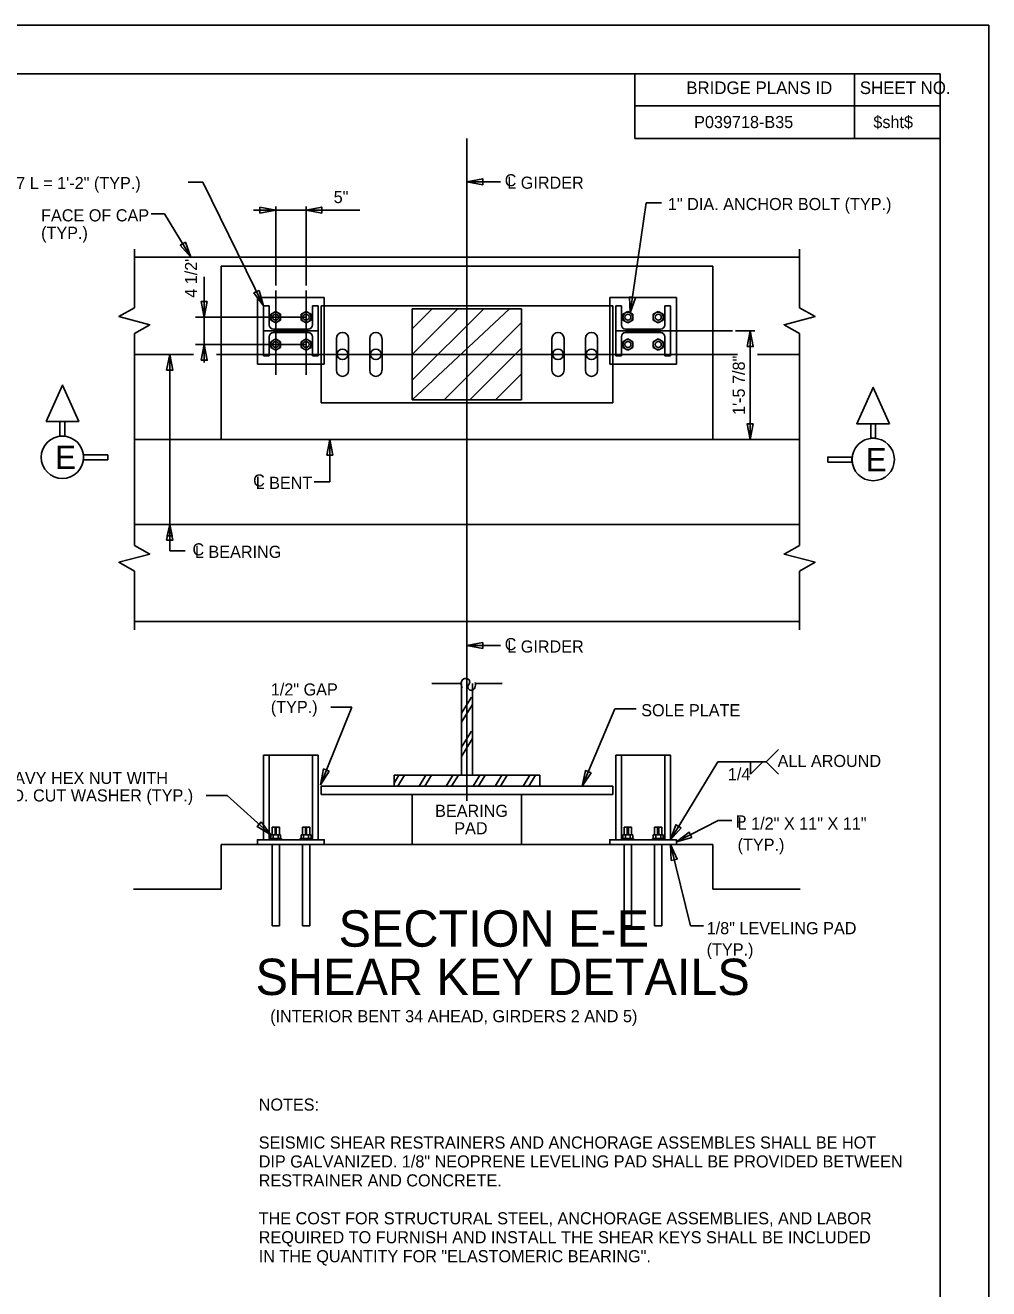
# Model space of a CAD drawing. Extents: x -144.4 to -96.3, y -117.1 to -87.8.
# Drawn here: x -109.69 to -96.47, y -105.14 to -87.8 of the extents above; entities that cross this region are included whole.
import ezdxf

# ---------------------------------------------------------------- set-up
doc = ezdxf.new("R2010")
doc.units = 0
for name, color, linetype in [('BR_AUTO DIMENSION', 7, 'Continuous'), ('BR_BORDER LINES', 7, 'Continuous'), ('BR_CENTER LINE BASELINE', 7, 'Continuous'), ('BR_CENTER LINES', 7, 'Continuous'), ('BR_CONCRETE', 7, 'Continuous'), ('BR_STRUCTURAL STEEL', 7, 'Continuous'), ('BR_TABLE LINES', 7, 'Continuous'), ('BR_TEXT', 7, 'Continuous'), ('Default', 7, 'Continuous'), ('Level 31', 7, 'Continuous')]:
    doc.layers.add(name, color=color, linetype=linetype)

msp = doc.modelspace()

# ---------------------------------------------------------------- linework, layer by layer
at = {"layer": 'BR_AUTO DIMENSION'}
for p, q in [((-107.459, -89.956), (-107.259, -89.956)), ((-107.259, -89.956), (-106.423, -91.651)), ((-103.632, -89.949), (-103.172, -89.949)), ((-106.257, -91.371), (-106.257, -90.287)), ((-105.84, -91.371), (-105.84, -90.287)), ((-101.39, -91.748), (-101.174, -90.239)), ((-101.174, -90.239), (-100.961, -90.239)), ((-107.966, -90.388), (-107.781, -90.388)), ((-107.781, -90.388), (-107.42, -90.984)), ((-106.562, -90.338), (-105.104, -90.338)), ((-108.195, -91.677), (-108.195, -90.874)), ((-99.068, -91.677), (-99.068, -90.874)), ((-107.238, -91.252), (-107.238, -92.429)), ((-108.195, -92.854), (-108.195, -92.031)), ((-99.946, -91.995), (-99.681, -91.995)), ((-99.743, -91.995), (-99.743, -93.484)), ((-99.068, -92.854), (-99.068, -92.031)), ((-107.712, -95.011), (-107.712, -92.317)), ((-108.195, -92.854), (-108.195, -94.114)), ((-99.068, -92.854), (-99.068, -94.114)), ((-105.515, -94.065), (-105.515, -93.484)), ((-99.881, -93.484), (-99.681, -93.484)), ((-108.195, -94.114), (-108.195, -94.937)), ((-105.728, -94.065), (-105.515, -94.065)), ((-99.068, -94.114), (-99.068, -94.937)), ((-107.499, -95.011), (-107.712, -95.011)), ((-108.195, -95.291), (-108.195, -96.094)), ((-99.068, -95.291), (-99.068, -96.094)), ((-103.632, -96.312), (-103.172, -96.312)), ((-105.214, -97.155), (-105.64, -98.221)), ((-105.502, -97.155), (-105.214, -97.155)), ((-101.601, -97.18), (-102.051, -98.241)), ((-101.309, -97.18), (-101.601, -97.18)), ((-99.356, -97.738), (-99.525, -97.906)), ((-100.188, -97.906), (-100.84, -98.975)), ((-100.188, -97.906), (-99.525, -97.906)), ((-99.572, -97.906), (-99.74, -98.074)), ((-99.74, -97.906), (-99.74, -98.074)), ((-99.525, -97.906), (-99.356, -98.074)), ((-107.211, -98.369), (-106.923, -98.369)), ((-106.923, -98.369), (-106.324, -98.907)), ((-104.382, -98.354), (-104.382, -99.042)), ((-104.382, -98.354), (-102.882, -98.354)), ((-102.882, -98.354), (-102.882, -99.042)), ((-100.182, -98.711), (-100.757, -99.005)), ((-99.996, -98.711), (-100.182, -98.711)), ((-100.838, -99.042), (-100.563, -100.157)), ((-100.563, -100.157), (-100.386, -100.157))]:
    msp.add_line(p, q, dxfattribs=at)
for points in [[(-103.416, -89.991), (-103.632, -89.949), (-103.416, -89.907)], [(-106.473, -90.297), (-106.257, -90.338), (-106.473, -90.38)], [(-105.624, -90.38), (-105.84, -90.338), (-105.624, -90.297)], [(-107.497, -90.778), (-107.42, -90.984), (-107.568, -90.821)], [(-106.482, -91.439), (-106.423, -91.651), (-106.556, -91.475)], [(-107.196, -91.591), (-107.238, -91.807), (-107.279, -91.591)], [(-101.318, -91.54), (-101.39, -91.748), (-101.4, -91.529)], [(-99.785, -92.211), (-99.743, -91.995), (-99.702, -92.211)], [(-107.279, -92.398), (-107.238, -92.182), (-107.196, -92.398)], [(-107.754, -92.534), (-107.712, -92.317), (-107.671, -92.534)], [(-99.702, -93.268), (-99.743, -93.484), (-99.785, -93.268)], [(-105.557, -93.7), (-105.515, -93.484), (-105.474, -93.7)], [(-107.754, -94.867), (-107.712, -94.651), (-107.671, -94.867)], [(-107.676, -94.807), (-107.712, -94.651), (-107.748, -94.807)], [(-103.416, -96.353), (-103.632, -96.312), (-103.416, -96.27)], [(-105.522, -98.036), (-105.64, -98.221), (-105.599, -98.005)], [(-101.928, -98.058), (-102.051, -98.241), (-102.005, -98.026)], [(-106.457, -98.732), (-106.324, -98.907), (-106.513, -98.794)], [(-100.692, -98.812), (-100.84, -98.975), (-100.763, -98.769)], [(-100.545, -98.944), (-100.757, -99.005), (-100.583, -98.87)], [(-100.827, -99.262), (-100.838, -99.042), (-100.746, -99.242)]]:
    msp.add_lwpolyline(points, close=True, dxfattribs=at)
for points in [[(-108.195, -91.677), (-108.41, -91.8), (-107.985, -91.911), (-108.195, -92.031)], [(-99.068, -91.677), (-98.853, -91.8), (-99.279, -91.911), (-99.068, -92.031)], [(-108.195, -95.291), (-108.41, -95.168), (-107.985, -95.057), (-108.195, -94.937)], [(-99.068, -95.291), (-98.853, -95.168), (-99.279, -95.057), (-99.068, -94.937)]]:
    msp.add_lwpolyline(points, dxfattribs=at)
at = {"layer": 'BR_BORDER LINES'}
for p, q in [((-97.136, -88.468), (-141.912, -88.468)), ((-101.329, -89.354), (-101.329, -88.468)), ((-98.315, -89.354), (-98.315, -88.468)), ((-97.136, -116.398), (-97.136, -88.468)), ((-101.329, -88.906), (-97.136, -88.906)), ((-98.315, -88.906), (-97.136, -88.906)), ((-97.136, -89.354), (-101.329, -89.354))]:
    msp.add_line(p, q, dxfattribs=at)
at = {"layer": 'BR_CENTER LINE BASELINE'}
for centre in [(-105.34, -92.317), (-104.882, -92.317), (-102.382, -92.317), (-101.923, -92.317)]:
    msp.add_circle(centre, 0.0729, dxfattribs=at)
at = {"layer": 'BR_CENTER LINES'}
for p, q in [((-103.632, -89.354), (-103.632, -98.44)), ((-106.257, -91.439), (-106.257, -92.6)), ((-105.84, -91.439), (-105.84, -92.6)), ((-105.84, -91.807), (-107.36, -91.807)), ((-100.84, -91.995), (-99.989, -91.995)), ((-105.84, -92.182), (-107.36, -92.182)), ((-108.195, -92.317), (-107.383, -92.317)), ((-107.07, -92.317), (-99.917, -92.317)), ((-99.645, -92.317), (-99.068, -92.317)), ((-99.068, -93.484), (-108.195, -93.484)), ((-108.195, -94.651), (-99.068, -94.651))]:
    msp.add_line(p, q, dxfattribs=at)
at = {"layer": 'BR_CONCRETE'}
for p, q in [((-108.195, -90.984), (-99.068, -90.984)), ((-107.007, -91.109), (-100.257, -91.109)), ((-107.007, -93.484), (-107.007, -91.109)), ((-100.257, -93.484), (-100.257, -91.109)), ((-107.007, -93.484), (-100.257, -93.484)), ((-108.195, -95.984), (-99.068, -95.984)), ((-107.007, -99.042), (-107.007, -99.653)), ((-107.007, -99.042), (-100.257, -99.042)), ((-100.257, -99.042), (-100.257, -99.653)), ((-107.007, -99.653), (-108.207, -99.653)), ((-99.057, -99.653), (-100.257, -99.653))]:
    msp.add_line(p, q, dxfattribs=at)
at = {"layer": 'BR_STRUCTURAL STEEL'}
for p, q in [((-106.507, -91.536), (-106.507, -92.453)), ((-105.59, -91.536), (-106.507, -91.536)), ((-106.345, -91.651), (-106.423, -91.651)), ((-106.423, -91.651), (-106.423, -92.338)), ((-106.345, -91.651), (-106.345, -91.914)), ((-105.673, -91.651), (-105.751, -91.651)), ((-105.751, -91.651), (-105.751, -91.914)), ((-105.673, -91.651), (-105.673, -92.338)), ((-105.632, -91.651), (-105.632, -92.984)), ((-101.632, -91.651), (-105.632, -91.651)), ((-105.59, -91.536), (-105.59, -91.651)), ((-105.59, -91.651), (-105.59, -92.453)), ((-101.673, -91.536), (-101.673, -91.651)), ((-101.673, -91.536), (-100.757, -91.536)), ((-101.673, -91.651), (-101.673, -92.453)), ((-101.632, -91.651), (-101.632, -92.984)), ((-101.59, -91.651), (-101.59, -92.338)), ((-101.59, -91.651), (-101.512, -91.651)), ((-101.512, -91.651), (-101.512, -91.914)), ((-100.918, -91.651), (-100.918, -91.914)), ((-100.918, -91.651), (-100.84, -91.651)), ((-100.84, -91.651), (-100.84, -92.338)), ((-100.757, -91.536), (-100.757, -92.453)), ((-106.257, -91.729), (-106.324, -91.768)), ((-106.324, -91.846), (-106.324, -91.768)), ((-106.257, -91.885), (-106.324, -91.846)), ((-106.189, -91.768), (-106.257, -91.729)), ((-106.189, -91.846), (-106.257, -91.885)), ((-106.189, -91.846), (-106.189, -91.768)), ((-105.84, -91.729), (-105.908, -91.768)), ((-105.908, -91.846), (-105.908, -91.768)), ((-105.84, -91.885), (-105.908, -91.846)), ((-105.772, -91.768), (-105.84, -91.729)), ((-105.772, -91.846), (-105.84, -91.885)), ((-105.772, -91.846), (-105.772, -91.768)), ((-101.491, -91.768), (-101.423, -91.729)), ((-101.491, -91.846), (-101.491, -91.768)), ((-101.491, -91.846), (-101.423, -91.885)), ((-101.423, -91.729), (-101.356, -91.768)), ((-101.423, -91.885), (-101.356, -91.846)), ((-101.356, -91.846), (-101.356, -91.768)), ((-101.074, -91.768), (-101.007, -91.729)), ((-101.074, -91.846), (-101.074, -91.768)), ((-101.074, -91.846), (-101.007, -91.885)), ((-101.007, -91.729), (-100.939, -91.768)), ((-101.007, -91.885), (-100.939, -91.846)), ((-100.939, -91.846), (-100.939, -91.768)), ((-106.423, -91.995), (-105.673, -91.995)), ((-106.288, -91.971), (-105.809, -91.971)), ((-106.288, -92.018), (-105.809, -92.018)), ((-100.84, -91.995), (-101.59, -91.995)), ((-100.975, -91.971), (-101.455, -91.971)), ((-100.975, -92.018), (-101.455, -92.018)), ((-106.345, -92.075), (-106.345, -92.338)), ((-106.257, -92.104), (-106.324, -92.143)), ((-106.324, -92.221), (-106.324, -92.143)), ((-106.189, -92.143), (-106.257, -92.104)), ((-106.189, -92.221), (-106.189, -92.143)), ((-105.84, -92.104), (-105.908, -92.143)), ((-105.908, -92.221), (-105.908, -92.143)), ((-105.772, -92.143), (-105.84, -92.104)), ((-105.772, -92.221), (-105.772, -92.143)), ((-105.751, -92.075), (-105.751, -92.338)), ((-105.423, -92.099), (-105.423, -92.536)), ((-105.257, -92.099), (-105.257, -92.536)), ((-104.965, -92.099), (-104.965, -92.536)), ((-104.798, -92.099), (-104.798, -92.536)), ((-102.465, -92.099), (-102.465, -92.536)), ((-102.298, -92.099), (-102.298, -92.536)), ((-102.007, -92.099), (-102.007, -92.536)), ((-101.84, -92.099), (-101.84, -92.536)), ((-101.512, -92.075), (-101.512, -92.338)), ((-101.491, -92.143), (-101.423, -92.104)), ((-101.491, -92.221), (-101.491, -92.143)), ((-101.423, -92.104), (-101.356, -92.143)), ((-101.356, -92.221), (-101.356, -92.143)), ((-101.074, -92.143), (-101.007, -92.104)), ((-101.074, -92.221), (-101.074, -92.143)), ((-101.007, -92.104), (-100.939, -92.143)), ((-100.939, -92.221), (-100.939, -92.143)), ((-100.918, -92.075), (-100.918, -92.338)), ((-106.345, -92.338), (-106.423, -92.338)), ((-106.257, -92.26), (-106.324, -92.221)), ((-106.189, -92.221), (-106.257, -92.26)), ((-105.84, -92.26), (-105.908, -92.221)), ((-105.772, -92.221), (-105.84, -92.26)), ((-105.673, -92.338), (-105.751, -92.338)), ((-101.59, -92.338), (-101.512, -92.338)), ((-101.491, -92.221), (-101.423, -92.26)), ((-101.423, -92.26), (-101.356, -92.221)), ((-101.074, -92.221), (-101.007, -92.26)), ((-101.007, -92.26), (-100.939, -92.221)), ((-100.918, -92.338), (-100.84, -92.338)), ((-105.632, -92.453), (-106.507, -92.453)), ((-105.59, -92.453), (-105.632, -92.453)), ((-101.673, -92.453), (-101.632, -92.453)), ((-101.632, -92.453), (-100.757, -92.453)), ((-101.632, -92.984), (-105.632, -92.984)), ((-103.707, -96.831), (-103.707, -98.091)), ((-103.557, -96.831), (-103.557, -98.091)), ((-103.707, -97.24), (-103.571, -97.019)), ((-103.707, -97.364), (-103.557, -97.12)), ((-103.707, -97.707), (-103.571, -97.486)), ((-103.707, -97.832), (-103.557, -97.587)), ((-106.423, -97.817), (-106.423, -98.975)), ((-106.423, -97.817), (-105.673, -97.817)), ((-106.345, -97.817), (-106.345, -98.975)), ((-105.751, -97.817), (-105.751, -98.975)), ((-105.673, -97.817), (-105.673, -98.975)), ((-101.59, -97.817), (-101.59, -98.975)), ((-101.59, -97.817), (-100.84, -97.817)), ((-101.512, -97.817), (-101.512, -98.975)), ((-100.918, -97.817), (-100.918, -98.975)), ((-100.84, -97.817), (-100.84, -98.975)), ((-104.632, -98.091), (-104.632, -98.241)), ((-104.632, -98.091), (-102.632, -98.091)), ((-104.632, -98.199), (-104.566, -98.091)), ((-104.581, -98.241), (-104.489, -98.091)), ((-104.288, -98.241), (-104.196, -98.091)), ((-104.212, -98.241), (-104.12, -98.091)), ((-103.918, -98.241), (-103.826, -98.091)), ((-103.842, -98.241), (-103.75, -98.091)), ((-103.548, -98.241), (-103.456, -98.091)), ((-103.472, -98.241), (-103.38, -98.091)), ((-103.246, -98.241), (-103.154, -98.091)), ((-103.17, -98.241), (-103.078, -98.091)), ((-102.861, -98.241), (-102.769, -98.091)), ((-102.785, -98.241), (-102.693, -98.091)), ((-102.632, -98.091), (-102.632, -98.241)), ((-105.632, -98.241), (-101.632, -98.241)), ((-105.632, -98.354), (-105.632, -98.241)), ((-104.632, -98.241), (-102.632, -98.241)), ((-101.632, -98.354), (-101.632, -98.241)), ((-105.632, -98.354), (-101.632, -98.354)), ((-106.336, -98.975), (-106.336, -98.958)), ((-106.336, -98.958), (-106.178, -98.958)), ((-106.324, -98.907), (-106.189, -98.907)), ((-106.324, -98.958), (-106.324, -98.907)), ((-106.307, -98.907), (-106.307, -98.805)), ((-106.307, -98.805), (-106.206, -98.805)), ((-106.307, -98.907), (-106.206, -98.907)), ((-106.29, -98.958), (-106.29, -98.907)), ((-106.274, -98.822), (-106.24, -98.822)), ((-106.274, -98.839), (-106.24, -98.839)), ((-106.274, -98.856), (-106.24, -98.856)), ((-106.274, -98.873), (-106.24, -98.873)), ((-106.274, -98.89), (-106.24, -98.89)), ((-106.223, -98.907), (-106.223, -98.958)), ((-106.206, -98.805), (-106.206, -98.907)), ((-106.189, -98.907), (-106.189, -98.958)), ((-106.178, -98.975), (-106.178, -98.958)), ((-105.919, -98.975), (-105.919, -98.958)), ((-105.919, -98.958), (-105.761, -98.958)), ((-105.908, -98.907), (-105.772, -98.907)), ((-105.908, -98.958), (-105.908, -98.907)), ((-105.891, -98.907), (-105.891, -98.805)), ((-105.891, -98.805), (-105.789, -98.805)), ((-105.891, -98.907), (-105.789, -98.907)), ((-105.874, -98.958), (-105.874, -98.907)), ((-105.857, -98.822), (-105.823, -98.822)), ((-105.857, -98.839), (-105.823, -98.839)), ((-105.857, -98.856), (-105.823, -98.856)), ((-105.857, -98.873), (-105.823, -98.873)), ((-105.857, -98.89), (-105.823, -98.89)), ((-105.806, -98.907), (-105.806, -98.958)), ((-105.789, -98.805), (-105.789, -98.907)), ((-105.772, -98.907), (-105.772, -98.958)), ((-105.761, -98.975), (-105.761, -98.958)), ((-101.502, -98.975), (-101.502, -98.958)), ((-101.502, -98.958), (-101.344, -98.958)), ((-101.491, -98.907), (-101.356, -98.907)), ((-101.491, -98.958), (-101.491, -98.907)), ((-101.474, -98.907), (-101.474, -98.805)), ((-101.474, -98.805), (-101.373, -98.805)), ((-101.474, -98.907), (-101.373, -98.907)), ((-101.457, -98.958), (-101.457, -98.907)), ((-101.44, -98.822), (-101.406, -98.822)), ((-101.44, -98.839), (-101.406, -98.839)), ((-101.44, -98.856), (-101.406, -98.856)), ((-101.44, -98.873), (-101.406, -98.873)), ((-101.44, -98.89), (-101.406, -98.89)), ((-101.39, -98.907), (-101.39, -98.958)), ((-101.373, -98.805), (-101.373, -98.907)), ((-101.356, -98.907), (-101.356, -98.958)), ((-101.344, -98.975), (-101.344, -98.958)), ((-101.086, -98.975), (-101.086, -98.958)), ((-101.086, -98.958), (-100.928, -98.958)), ((-101.074, -98.907), (-100.939, -98.907)), ((-101.074, -98.958), (-101.074, -98.907)), ((-101.057, -98.907), (-101.057, -98.805)), ((-101.057, -98.805), (-100.956, -98.805)), ((-101.057, -98.907), (-100.956, -98.907)), ((-101.04, -98.958), (-101.04, -98.907)), ((-101.024, -98.822), (-100.99, -98.822)), ((-101.024, -98.839), (-100.99, -98.839)), ((-101.024, -98.856), (-100.99, -98.856)), ((-101.024, -98.873), (-100.99, -98.873)), ((-101.024, -98.89), (-100.99, -98.89)), ((-100.973, -98.907), (-100.973, -98.958)), ((-100.956, -98.805), (-100.956, -98.907)), ((-100.939, -98.907), (-100.939, -98.958)), ((-100.928, -98.975), (-100.928, -98.958)), ((-106.358, -98.975), (-106.155, -98.975)), ((-106.307, -99.042), (-106.307, -100.156)), ((-106.206, -99.042), (-106.206, -100.156)), ((-105.891, -99.042), (-105.891, -100.156)), ((-105.789, -99.042), (-105.789, -100.156)), ((-101.525, -98.975), (-101.322, -98.975)), ((-101.474, -99.042), (-101.474, -100.156)), ((-101.373, -99.042), (-101.373, -100.156)), ((-101.057, -99.042), (-101.057, -100.156)), ((-100.956, -99.042), (-100.956, -100.156)), ((-106.307, -100.156), (-106.206, -100.156)), ((-105.891, -100.156), (-105.789, -100.156)), ((-101.474, -100.156), (-101.373, -100.156)), ((-101.057, -100.156), (-100.956, -100.156))]:
    msp.add_line(p, q, dxfattribs=at)
for points in [[(-105.59, -99.042), (-105.59, -98.975), (-106.507, -98.975), (-106.507, -99.042)], [(-100.757, -99.042), (-100.757, -98.975), (-101.673, -98.975), (-101.673, -99.042)]]:
    msp.add_lwpolyline(points, close=True, dxfattribs=at)
for centre, radius in [((-106.257, -91.807), 0.0677), ((-106.257, -91.807), 0.0417), ((-105.84, -91.807), 0.0677), ((-105.84, -91.807), 0.0417), ((-101.423, -91.807), 0.0677), ((-101.423, -91.807), 0.0417), ((-101.007, -91.807), 0.0677), ((-101.007, -91.807), 0.0417), ((-106.257, -92.182), 0.0677), ((-106.257, -92.182), 0.0417), ((-105.84, -92.182), 0.0677), ((-105.84, -92.182), 0.0417), ((-101.423, -92.182), 0.0677), ((-101.423, -92.182), 0.0417), ((-101.007, -92.182), 0.0677), ((-101.007, -92.182), 0.0417)]:
    msp.add_circle(centre, radius, dxfattribs=at)
for centre, radius, start, end in [((-106.288, -91.914), 0.0573, 180, 270), ((-106.288, -92.075), 0.0573, 90, 180), ((-105.809, -91.914), 0.0573, 270, 360), ((-105.809, -92.075), 0.0573, 360, 90), ((-105.34, -92.099), 0.0833, 0, 180), ((-104.882, -92.099), 0.0833, 0, 180), ((-102.382, -92.099), 0.0833, 0, 180), ((-101.923, -92.099), 0.0833, 0, 180), ((-101.455, -91.914), 0.0573, 180, 270), ((-101.455, -92.075), 0.0573, 90, 180), ((-100.975, -91.914), 0.0573, 270, 360), ((-100.975, -92.075), 0.0573, 360, 90), ((-105.34, -92.536), 0.0833, 180, 0), ((-104.882, -92.536), 0.0833, 180, 0), ((-102.382, -92.536), 0.0833, 180, 0), ((-101.923, -92.536), 0.0833, 180, 0)]:
    msp.add_arc(centre, radius, start, end, dxfattribs=at)
at = {"layer": 'BR_TABLE LINES'}
for p, q in [((-102.882, -91.692), (-104.382, -91.692)), ((-104.382, -92.942), (-104.382, -91.692)), ((-102.882, -91.692), (-102.882, -92.942)), ((-102.882, -92.942), (-104.382, -92.942))]:
    msp.add_line(p, q, dxfattribs=at)
at = {"layer": 'BR_TEXT'}
for p, q in [((-104.116, -96.831), (-103.711, -96.831)), ((-103.517, -96.831), (-103.148, -96.831))]:
    msp.add_line(p, q, dxfattribs=at)
for points in [[(-109.409, -93.238), (-109.185, -92.739), (-108.96, -93.238)], [(-97.832, -93.27), (-98.056, -92.77), (-98.281, -93.27)], [(-109.151, -93.438), (-109.151, -93.238), (-109.218, -93.238), (-109.218, -93.438)], [(-98.09, -93.469), (-98.09, -93.27), (-98.023, -93.27), (-98.023, -93.469)], [(-108.561, -93.762), (-108.561, -93.696), (-108.894, -93.696), (-108.894, -93.762)], [(-98.68, -93.794), (-98.68, -93.727), (-98.348, -93.727), (-98.348, -93.794)]]:
    msp.add_lwpolyline(points, close=True, dxfattribs=at)
for centre in [(-109.185, -93.729), (-98.056, -93.76)]:
    msp.add_circle(centre, 0.291, dxfattribs=at)
for centre, radius, start, end in [((-103.604, -96.842), 0.108, 155.6187, 208.3414), ((-103.647, -96.823), 0.0609, 83.2422, 155.6187), ((-103.645, -96.813), 0.0511, 316.8236, 83.2422), ((-103.574, -96.88), 0.0465, 136.8236, 275.5224), ((-103.623, -96.85), 0.107, 335.6333, 17.6449), ((-103.575, -96.871), 0.0548, 275.5224, 335.6333)]:
    msp.add_arc(centre, radius, start, end, dxfattribs=at)
at = {"layer": 'Default'}
for p, q in [((-104.382, -92.942), (-103.048, -91.692)), ((-104.382, -92.672), (-103.402, -91.692)), ((-104.382, -92.319), (-103.755, -91.692)), ((-104.382, -91.965), (-104.109, -91.692)), ((-103.945, -92.942), (-102.882, -91.879)), ((-103.591, -92.942), (-102.882, -92.233)), ((-103.238, -92.942), (-102.882, -92.586))]:
    msp.add_line(p, q, dxfattribs=at)
at = {"layer": 'Level 31'}
msp.add_lwpolyline([(-144.35, -117.062), (-96.47, -117.062), (-96.47, -87.803), (-144.35, -87.803)], close=True, dxfattribs=at)

# ---------------------------------------------------------------- texts
at = {"layer": 'BR_AUTO DIMENSION'}
for s, height, p in [('W8X67 L = 1\'-2" (TYP.)', 0.16625, (-110.424, -90.05)), ('C', 0.166, (-103.114, -90.012)), ('L GIRDER', 0.1662, (-103.079, -90.045)), ('5"', 0.1662, (-105.461, -90.242)), ('FACE OF CAP', 0.16625, (-109.477, -90.493)), ('(TYP.)', 0.1662, (-109.477, -90.733)), ('C', 0.166, (-106.567, -94.13)), ('L BENT', 0.1662, (-106.532, -94.163)), ('C', 0.166, (-107.399, -95.075)), ('L BEARING', 0.1662, (-107.365, -95.109)), ('C', 0.166, (-103.114, -96.375)), ('L GIRDER', 0.1662, (-103.079, -96.408)), ('1/2" GAP ', 0.1662, (-106.324, -96.997)), ('(TYP.)', 0.1662, (-106.324, -97.237)), ('SOLE PLATE', 0.1662, (-101.24, -97.282)), ('HEAVY HEX NUT WITH ', 0.16625, (-110.156, -98.211)), ('STD. CUT WASHER (TYP.)', 0.16625, (-110.156, -98.451)), ('BEARING', 0.1662, (-104.069, -98.662)), ('PAD', 0.1662, (-103.806, -98.901)), ('(INTERIOR BENT 34 AHEAD, GIRDERS 2 AND 5)', 0.16625, (-106.333, -101.479)), ('NOTES:', 0.1662, (-106.49, -102.692)), ('SEISMIC SHEAR RESTRAINERS AND ANCHORAGE ASSEMBLES SHALL BE HOT', 0.16625, (-106.49, -103.212)), ('DIP GALVANIZED. 1/8" NEOPRENE LEVELING PAD SHALL BE PROVIDED BETWEEN', 0.16625, (-106.49, -103.472)), ('RESTRAINER AND CONCRETE.', 0.16625, (-106.49, -103.732)), ('THE COST FOR STRUCTURAL STEEL, ANCHORAGE ASSEMBLIES, AND LABOR', 0.16625, (-106.49, -104.252)), ('REQUIRED TO FURNISH AND INSTALL THE SHEAR KEYS SHALL BE INCLUDED', 0.16625, (-106.49, -104.512)), ('IN THE QUANTITY FOR "ELASTOMERIC BEARING".', 0.16625, (-106.49, -104.772))]:
    msp.add_text(s, height=height, dxfattribs=at).set_placement(p)
msp.add_text('1\'-5 7/8"', height=0.1662, rotation=90, dxfattribs=at).set_placement((-99.818, -93.149))
at = {"layer": 'BR_TEXT'}
for s, height, p in [('BRIDGE PLANS ID', 0.1729, (-100.622, -88.746)), ('SHEET NO.', 0.1729, (-98.24, -88.746)), ('P039718-B35', 0.16625, (-100.514, -89.213)), ('$sht$', 0.1662, (-98.054, -89.213)), ('1" DIA. ANCHOR BOLT (TYP.)', 0.16625, (-100.874, -90.338)), ('E', 0.319, (-109.284, -93.889)), ('E', 0.319, (-98.156, -93.92)), ('ALL AROUND', 0.1662, (-99.368, -97.978)), ('1/4', 0.1662, (-100.051, -98.159)), ('P', 0.166, (-99.943, -98.808)), ('L 1/2" X 11" X 11"', 0.16625, (-99.917, -98.836)), ('(TYP.)', 0.1662, (-99.917, -99.127)), ('SECTION E-E', 0.49875, (-105.394, -100.443)), ('1/8" LEVELING PAD', 0.16625, (-100.342, -100.272)), ('(TYP.)', 0.1662, (-100.342, -100.564)), ('SHEAR KEY DETAILS', 0.49875, (-106.533, -101.106))]:
    msp.add_text(s, height=height, dxfattribs=at).set_placement(p)
msp.add_text('4 1/2"', height=0.1662, rotation=90, dxfattribs=at).set_placement((-107.336, -91.541))

doc.saveas('drawing.dxf')
